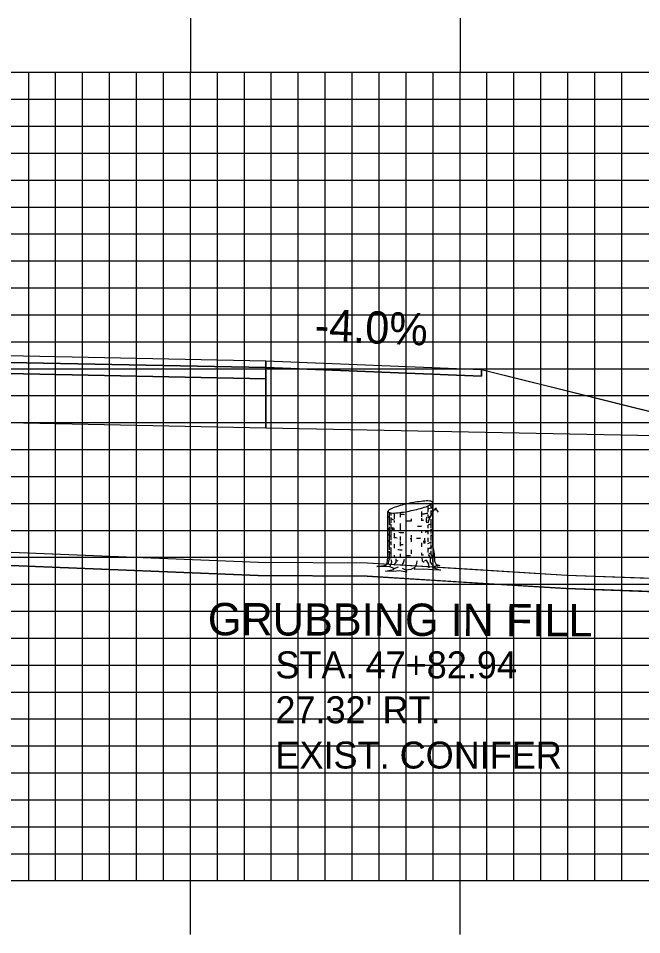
# Model space of a CAD drawing. Extents: x 1754708 to 1755051, y 442591 to 442811.
# Drawn here: x 1754887.13 to 1754910.25, y 442685.31 to 442719.32 of the extents above; entities that cross this region are included whole.
import ezdxf

# ---------------------------------------------------------------- set-up
doc = ezdxf.new("R2010")
doc.units = 0
for name, color, linetype in [('ANNOTATION', 7, 'Continuous'), ('D_Roadway_Edge_Shoulder', 7, 'Continuous'), ('D_Roadway_Edge_TW', 7, 'Continuous'), ('D_Roadway_Pavement', 7, 'Continuous'), ('D_Roadway_SlopeLines', 7, 'Continuous'), ('D_Roadway_SubGrade', 7, 'Continuous'), ('D_Text_Monospaced', 7, 'Continuous'), ('DIMENSIONS', 7, 'Continuous'), ('GRUBBING IN FILL', 7, 'Continuous'), ('M_Trees_Conifer_Pay', 7, 'Continuous'), ('MAJOR', 7, 'Continuous'), ('MINOR', 7, 'Continuous'), ('S_Roadway_Centerline', 7, 'Continuous')]:
    doc.layers.add(name, color=color, linetype=linetype)

msp = doc.modelspace()

# ---------------------------------------------------------------- linework, layer by layer
at = {"layer": 'D_Roadway_Edge_Shoulder'}
msp.add_lwpolyline([(1754896.317, 442706.606), (1754904.317, 442706.286), (1754904.317, 442706.036), (1754896.317, 442706.356)], close=True, dxfattribs=at)
at = {"layer": 'D_Roadway_Edge_TW'}
msp.add_lwpolyline([(1754885.517, 442706.822), (1754896.317, 442706.606), (1754896.317, 442706.356), (1754885.517, 442706.572)], close=True, dxfattribs=at)
at = {"layer": 'D_Roadway_Pavement'}
msp.add_lwpolyline([(1754885.517, 442706.572), (1754896.317, 442706.356), (1754896.317, 442705.94), (1754885.517, 442706.156)], close=True, dxfattribs=at)
msp.add_lwpolyline([(1754896.317, 442706.356), (1754896.317, 442705.94)], dxfattribs=at)
msp.add_lwpolyline([(1754896.317, 442706.356), (1754896.317, 442705.94)], dxfattribs=at)
msp.add_lwpolyline([(1754896.317, 442706.356), (1754896.317, 442705.94)], dxfattribs=at)
at = {"layer": 'D_Roadway_SlopeLines'}
msp.add_lwpolyline([(1754904.317, 442706.286), (1754916.317, 442703.286), (1754936.682, 442698.237)], dxfattribs=at)
at = {"layer": 'D_Roadway_SubGrade'}
for points in [[(1754896.317, 442705.94), (1754896.317, 442706.356), (1754904.317, 442706.036), (1754904.317, 442706.286), (1754914.492, 442703.743), (1754896.317, 442704.106)], [(1754885.517, 442706.156), (1754896.317, 442705.94), (1754896.317, 442704.106), (1754885.517, 442704.322)]]:
    msp.add_lwpolyline(points, close=True, dxfattribs=at)
at = {"layer": 'DIMENSIONS'}
msp.add_line((1754904.317, 442706.286), (1754936.682, 442698.237), dxfattribs=at)
at = {"layer": 'GRUBBING IN FILL'}
msp.add_lwpolyline([(1754843.343, 442701.662), (1754848.865, 442700.485), (1754852.113, 442699.756), (1754854.166, 442698.979), (1754857.625, 442698.75), (1754875.218, 442699.401), (1754875.984, 442699.448), (1754878.886, 442699.328), (1754896.033, 442698.632), (1754900.072, 442698.607), (1754907.451, 442698.155), (1754914.492, 442697.896)], dxfattribs=at)
msp.add_lwpolyline([(1754843.343, 442701.662), (1754848.865, 442700.485), (1754852.113, 442699.756), (1754854.166, 442698.979), (1754857.625, 442698.75), (1754875.218, 442699.401), (1754875.984, 442699.448), (1754878.886, 442699.328), (1754896.033, 442698.632), (1754900.072, 442698.607), (1754907.451, 442698.155), (1754914.492, 442697.896)], dxfattribs=at)
msp.add_lwpolyline([(1754873.517, 442699.839), (1754875.194, 442699.901), (1754875.979, 442699.949), (1754877.443, 442699.888), (1754878.907, 442699.828), (1754887.476, 442699.48), (1754896.045, 442699.132), (1754900.089, 442699.107), (1754903.782, 442698.881), (1754907.475, 442698.655), (1754911.045, 442698.523), (1754914.492, 442698.396), (1754914.492, 442697.896), (1754910.971, 442698.026), (1754907.451, 442698.155), (1754903.761, 442698.381), (1754900.072, 442698.607), (1754896.033, 442698.632), (1754887.459, 442698.98), (1754878.886, 442699.328), (1754875.984, 442699.448), (1754873.517, 442699.338)], close=True, dxfattribs=at)
msp.add_lwpolyline([(1754873.517, 442699.839), (1754875.194, 442699.901), (1754875.979, 442699.949), (1754877.443, 442699.888), (1754878.907, 442699.828), (1754887.476, 442699.48), (1754896.045, 442699.132), (1754900.089, 442699.107), (1754903.782, 442698.881), (1754907.475, 442698.655), (1754911.045, 442698.523), (1754914.492, 442698.396), (1754914.492, 442697.896), (1754910.971, 442698.026), (1754907.451, 442698.155), (1754903.761, 442698.381), (1754900.072, 442698.607), (1754896.033, 442698.632), (1754887.459, 442698.98), (1754878.886, 442699.328), (1754875.984, 442699.448), (1754873.517, 442699.338)], close=True, dxfattribs=at)
at = {"layer": 'M_Trees_Conifer_Pay'}
for p, q in [((1754902.317, 442701.214), (1754902.317, 442700.991)), ((1754902.435, 442701.275), (1754902.435, 442701.113)), ((1754902.506, 442699.701), (1754902.506, 442701.348)), ((1754900.842, 442699.291), (1754900.842, 442701.012)), ((1754900.89, 442700.975), (1754900.89, 442700.504)), ((1754900.948, 442700.964), (1754900.948, 442700.866)), ((1754901.073, 442700.956), (1754901.073, 442700.724)), ((1754901.293, 442700.976), (1754901.293, 442700.808)), ((1754902.089, 442701.018), (1754902.089, 442700.819)), ((1754902.317, 442700.903), (1754902.317, 442700.855)), ((1754902.435, 442701.045), (1754902.435, 442700.917)), ((1754900.948, 442700.792), (1754900.948, 442700.588)), ((1754900.948, 442700.53), (1754900.948, 442700.331)), ((1754901.073, 442700.683), (1754901.073, 442700.609)), ((1754901.293, 442700.571), (1754901.293, 442700.334)), ((1754901.699, 442700.745), (1754901.699, 442700.649)), ((1754902.089, 442700.761), (1754902.089, 442700.672)), ((1754902.317, 442700.52), (1754902.317, 442700.388)), ((1754902.375, 442700.72), (1754902.323, 442700.66)), ((1754902.435, 442700.73), (1754902.435, 442700.394)), ((1754900.89, 442700.439), (1754900.89, 442700.131)), ((1754900.948, 442700.283), (1754900.948, 442699.947)), ((1754901.073, 442700.205), (1754901.073, 442700.067)), ((1754902.089, 442700.325), (1754902.089, 442700.22)), ((1754902.317, 442700.277), (1754902.317, 442700.168)), ((1754902.435, 442700.357), (1754902.435, 442700.195)), ((1754900.89, 442700.084), (1754900.89, 442699.592)), ((1754900.948, 442699.894), (1754900.948, 442699.758)), ((1754901.293, 442700.09), (1754901.293, 442699.938)), ((1754901.293, 442699.894), (1754901.293, 442699.721)), ((1754901.699, 442700.131), (1754901.699, 442700.057)), ((1754901.699, 442700.032), (1754901.699, 442699.884)), ((1754902.089, 442699.853), (1754902.089, 442699.707)), ((1754902.317, 442700.032), (1754902.317, 442699.89)), ((1754902.435, 442700.147), (1754902.435, 442699.931)), ((1754902.435, 442699.9), (1754902.435, 442699.826)), ((1754900.89, 442699.538), (1754900.89, 442699.291)), ((1754900.948, 442699.659), (1754900.948, 442699.281)), ((1754901.073, 442699.795), (1754901.073, 442699.653)), ((1754901.699, 442699.592), (1754901.699, 442699.439)), ((1754902.317, 442699.663), (1754902.317, 442699.491)), ((1754902.435, 442699.785), (1754902.435, 442699.612)), ((1754901.073, 442699.392), (1754901.073, 442699.297)), ((1754901.293, 442699.443), (1754901.293, 442699.291)), ((1754902.089, 442699.474), (1754902.089, 442699.386)), ((1754901.073, 442698.897), (1754901.236, 442698.961)), ((1754901.51, 442698.833), (1754901.384, 442698.897))]:
    msp.add_line(p, q, dxfattribs=at)
for points in [[(1754902.323, 442700.846), (1754902.36, 442700.771), (1754902.407, 442700.829), (1754902.465, 442700.897), (1754902.558, 442701.09), (1754902.622, 442701.138), (1754902.653, 442701.144)], [(1754902.338, 442700.592), (1754902.375, 442700.72), (1754902.438, 442700.835), (1754902.469, 442700.903), (1754902.538, 442701.049)], [(1754902.552, 442701.079), (1754902.628, 442701.086), (1754902.7, 442700.987)], [(1754902.29, 442700.808), (1754902.259, 442700.724), (1754902.255, 442700.656), (1754902.286, 442700.592)], [(1754901.022, 442700.318), (1754901.016, 442700.413), (1754901.059, 442700.39), (1754901.059, 442700.296)], [(1754902.161, 442699.919), (1754902.173, 442699.842), (1754902.22, 442699.853), (1754902.208, 442700.02)], [(1754902.506, 442699.701), (1754902.558, 442699.439), (1754902.574, 442699.165), (1754902.632, 442699.04), (1754902.768, 442699.009), (1754902.537, 442698.972), (1754902.537, 442698.972), (1754902.543, 442698.924), (1754902.791, 442698.83), (1754902.516, 442698.846), (1754902.161, 442698.867), (1754901.839, 442698.856), (1754901.846, 442698.939), (1754901.697, 442698.856), (1754901.51, 442698.833), (1754901.535, 442698.766), (1754901.267, 442698.809), (1754901.046, 442698.782), (1754900.754, 442698.799), (1754901.043, 442698.856), (1754901.073, 442698.897), (1754900.911, 442698.955), (1754900.674, 442698.966), (1754900.433, 442698.966), (1754900.775, 442699.023), (1754900.816, 442699.104), (1754900.842, 442699.291)], [(1754902.432, 442699.558), (1754902.438, 442699.413), (1754902.485, 442699.344), (1754902.496, 442699.145)], [(1754900.89, 442699.243), (1754900.869, 442699.165), (1754900.849, 442699.071)], [(1754900.968, 442699.223), (1754900.974, 442699.107), (1754900.921, 442699.019), (1754900.911, 442698.955)], [(1754901.131, 442699.25), (1754901.131, 442699.118), (1754901.043, 442699.019)], [(1754901.358, 442699.009), (1754901.425, 442699.104), (1754901.452, 442699.243)], [(1754901.846, 442698.939), (1754901.92, 442699.081), (1754901.93, 442699.182)], [(1754902.096, 442699.308), (1754902.107, 442699.182), (1754902.181, 442699.138)], [(1754902.375, 442698.918), (1754902.36, 442699.056), (1754902.286, 442699.186)], [(1754902.333, 442699.413), (1754902.407, 442699.308), (1754902.412, 442699.134), (1754902.537, 442698.972)]]:
    msp.add_lwpolyline(points, dxfattribs=at)
for centre, radius, start, end in [((1754902.698, 442696.245), 5.179, 101.7194, 108.0594), ((1754902.698, 442696.245), 5.179, 95.3794, 101.7194), ((1754900.651, 442706.115), 5.179, 281.7194, 288.0594), ((1754902.288, 442700.603), 0.802, 79.2194, 95.3794), ((1754902.008, 442701.953), 0.802, 288.0594, 304.2194), ((1754902.391, 442701.144), 0.251, 71.0501, 79.2194), ((1754902.318, 442701.498), 0.251, 304.2194, 312.3887), ((1754902.375, 442701.316), 0.172, 300, 311.2506), ((1754902.446, 442701.304), 0.0817, 56.7194, 71.0501), ((1754902.431, 442701.373), 0.0817, 312.3887, 326.7194), ((1754902.447, 442701.233), 0.0624, 311.2506, 330), ((1754902.462, 442701.328), 0.0527, 46.923, 56.7194), ((1754902.476, 442701.344), 0.0314, 34.2194, 46.923), ((1754902.456, 442701.357), 0.0527, 326.7194, 336.5158), ((1754902.463, 442701.224), 0.0441, 330, 343.9485), ((1754902.48, 442701.346), 0.0264, 23.4074, 34.2194), ((1754902.475, 442701.349), 0.0314, 336.5158, 349.2194), ((1754902.484, 442701.348), 0.0226, 11.7194, 23.4074), ((1754902.473, 442701.221), 0.0334, 343.9485, 354.2151), ((1754902.484, 442701.348), 0.0226, 0.0315, 11.7194), ((1754902.48, 442701.348), 0.0264, 349.2194, 0.0315), ((1754900.875, 442700.834), 0.0334, 163.9485, 180), ((1754900.874, 442701.011), 0.0314, 156.5158, 169.2194), ((1754900.869, 442701.012), 0.0264, 169.2194, 180.0315), ((1754900.865, 442701.012), 0.0226, 180.0315, 191.7194), ((1754900.865, 442701.012), 0.0226, 191.7194, 203.4074), ((1754900.869, 442701.014), 0.0264, 203.4074, 214.2194), ((1754900.893, 442701.003), 0.0527, 146.7194, 156.5158), ((1754900.873, 442701.016), 0.0314, 214.2194, 226.923), ((1754900.918, 442700.987), 0.0817, 132.3887, 146.7194), ((1754900.887, 442701.032), 0.0527, 226.923, 236.7194), ((1754900.903, 442701.056), 0.0817, 236.7194, 251.0501), ((1754901.031, 442700.862), 0.251, 124.2194, 132.3887), ((1754900.958, 442701.216), 0.251, 251.0501, 259.2194), ((1754901.341, 442700.406), 0.802, 108.0594, 124.2194), ((1754901.061, 442701.757), 0.802, 259.2194, 275.3794), ((1754900.651, 442706.115), 5.179, 275.3794, 281.7194), ((1754901.675, 442705.024), 4.124, 264.6955, 266.7331), ((1754901.675, 442705.024), 4.124, 276.238, 278.1032), ((1754902.176, 442701.507), 0.571, 278.1032, 284.3667), ((1754902.176, 442701.661), 0.571, 284.4317, 292.4132), ((1754902.176, 442701.507), 0.571, 297.0237, 300), ((1754902.375, 442701.162), 0.172, 300, 311.2506), ((1754902.447, 442701.079), 0.0624, 311.2506, 330), ((1754902.463, 442701.07), 0.0441, 330, 343.9485), ((1754902.473, 442701.067), 0.0334, 343.9485, 354.2151), ((1754900.875, 442700.834), 0.0334, 180, 196.0515), ((1754900.885, 442700.837), 0.0441, 196.0515, 210), ((1754900.901, 442700.846), 0.0624, 210, 228.7494), ((1754900.973, 442700.929), 0.172, 228.7494, 240), ((1754901.172, 442701.274), 0.571, 240, 240.3367), ((1754901.174, 442701.063), 0.571, 240, 247.0587), ((1754901.172, 442701.274), 0.571, 246.8597, 257.9846), ((1754901.673, 442704.791), 4.124, 268.0751, 270), ((1754901.673, 442704.791), 4.124, 270, 270.3581), ((1754901.673, 442704.791), 4.124, 275.7849, 277.0558), ((1754902.175, 442701.063), 0.571, 284.4493, 297.0429), ((1754902.473, 442700.623), 0.0334, 343.9485, 354.2151), ((1754900.875, 442700.387), 0.0334, 163.9485, 180), ((1754900.875, 442700.387), 0.0334, 180, 196.0515), ((1754900.875, 442700.177), 0.0334, 163.9485, 180), ((1754900.875, 442700.177), 0.0334, 180, 196.0515), ((1754900.885, 442700.39), 0.0441, 196.0515, 210), ((1754900.885, 442700.18), 0.0441, 196.0515, 210), ((1754900.901, 442700.399), 0.0624, 210, 228.7494), ((1754900.973, 442700.482), 0.172, 228.7494, 240), ((1754901.172, 442700.827), 0.571, 240, 240.3367), ((1754901.673, 442704.345), 4.124, 264.081, 266.6676), ((1754901.675, 442704.58), 4.124, 273.7052, 275.9504), ((1754901.673, 442704.345), 4.124, 277.6125, 278.1032), ((1754902.174, 442700.827), 0.571, 278.1032, 286.9296), ((1754902.174, 442700.827), 0.571, 297.1896, 300), ((1754902.373, 442700.482), 0.172, 300, 311.2506), ((1754902.446, 442700.399), 0.0624, 311.2506, 330), ((1754902.462, 442700.39), 0.0441, 330, 343.9485), ((1754902.462, 442700.18), 0.0441, 330, 343.9485), ((1754902.472, 442700.387), 0.0334, 343.9485, 354.2151), ((1754902.472, 442700.177), 0.0334, 343.9485, 354.2151), ((1754900.875, 442699.94), 0.0334, 163.9485, 180), ((1754900.875, 442699.94), 0.0334, 180, 196.0515), ((1754900.885, 442699.943), 0.0441, 196.0515, 210), ((1754900.901, 442700.189), 0.0624, 210, 228.7494), ((1754900.901, 442699.953), 0.0624, 210, 228.7494), ((1754900.973, 442700.272), 0.172, 228.7494, 240), ((1754900.973, 442700.035), 0.172, 228.7494, 240), ((1754901.172, 442700.617), 0.571, 240, 246.8597), ((1754901.172, 442700.38), 0.571, 240, 246.8597), ((1754901.172, 442700.617), 0.571, 259.2707, 261.8968), ((1754901.673, 442704.135), 4.124, 261.8968, 263.1474), ((1754901.673, 442704.135), 4.124, 270, 270.3581), ((1754901.673, 442704.135), 4.124, 273.1493, 275.4569), ((1754902.174, 442700.38), 0.571, 285.3983, 297.1896), ((1754902.174, 442700.617), 0.571, 297.1896, 300), ((1754902.373, 442700.272), 0.172, 300, 311.2506), ((1754902.446, 442700.189), 0.0624, 311.2506, 330), ((1754900.875, 442699.743), 0.0334, 163.9485, 180), ((1754900.875, 442699.547), 0.0334, 163.9485, 180), ((1754900.875, 442699.547), 0.0334, 180, 196.0515), ((1754900.885, 442699.55), 0.0441, 196.0515, 210), ((1754900.901, 442699.559), 0.0624, 210, 228.7494), ((1754900.973, 442699.642), 0.172, 228.7494, 240), ((1754901.162, 442700.189), 0.571, 241.2369, 248.0268), ((1754901.172, 442699.987), 0.571, 240, 246.8597), ((1754901.673, 442703.7), 4.124, 263.4991, 265.8397), ((1754901.673, 442703.898), 4.124, 264.716, 266.3193), ((1754902.174, 442700.183), 0.571, 289.2907, 300), ((1754902.373, 442699.838), 0.172, 300, 311.2506), ((1754902.446, 442699.755), 0.0624, 311.2506, 330), ((1754902.462, 442699.746), 0.0441, 330, 343.9485), ((1754902.472, 442699.743), 0.0334, 343.9485, 354.2151), ((1754900.875, 442699.327), 0.0334, 163.9485, 180), ((1754900.875, 442699.327), 0.0334, 180, 196.0515), ((1754900.885, 442699.33), 0.0441, 196.0515, 210), ((1754900.901, 442699.339), 0.0624, 210, 228.7494), ((1754900.973, 442699.422), 0.172, 228.7494, 240), ((1754901.172, 442699.767), 0.571, 240, 244.5314), ((1754901.673, 442703.284), 4.124, 262.4438, 263.512), ((1754901.673, 442703.505), 4.124, 267.8117, 270), ((1754901.673, 442703.505), 4.124, 270, 270.1328), ((1754901.673, 442703.505), 4.124, 275.7849, 276.7896), ((1754901.673, 442703.284), 4.124, 277.3684, 278.1032), ((1754902.174, 442699.767), 0.571, 278.1032, 281.637), ((1754902.174, 442699.987), 0.571, 288.5067, 297.2721), ((1754902.373, 442699.422), 0.172, 300, 311.2506), ((1754902.446, 442699.339), 0.0624, 311.2506, 330), ((1754902.462, 442699.33), 0.0441, 330, 343.9485), ((1754902.472, 442699.327), 0.0334, 343.9485, 354.2151)]:
    msp.add_arc(centre, radius, start, end, dxfattribs=at)
at = {"layer": 'MAJOR'}
for p, q in [((1754893.517, 442719.316), (1754893.517, 442717.312)), ((1754903.517, 442719.316), (1754903.517, 442717.312)), ((1754733.517, 442717.312), (1755013.517, 442717.312)), ((1754733.517, 442717.312), (1755013.517, 442717.312)), ((1754893.517, 442687.312), (1754893.517, 442717.312)), ((1754903.517, 442687.312), (1754903.517, 442717.312)), ((1754733.517, 442712.312), (1755013.517, 442712.312)), ((1754733.517, 442707.312), (1755013.517, 442707.312)), ((1754733.517, 442702.312), (1755013.517, 442702.312)), ((1754733.517, 442697.312), (1755013.517, 442697.312)), ((1754733.517, 442692.312), (1755013.517, 442692.312)), ((1754733.517, 442687.312), (1755013.517, 442687.312)), ((1754733.517, 442687.312), (1755013.517, 442687.312)), ((1754893.517, 442685.308), (1754893.517, 442687.312)), ((1754903.517, 442685.308), (1754903.517, 442687.312))]:
    msp.add_line(p, q, dxfattribs=at)
at = {"layer": 'MINOR'}
for p, q in [((1754887.517, 442687.312), (1754887.517, 442717.312)), ((1754888.517, 442687.312), (1754888.517, 442717.312)), ((1754889.517, 442687.312), (1754889.517, 442717.312)), ((1754890.517, 442687.312), (1754890.517, 442717.312)), ((1754891.517, 442687.312), (1754891.517, 442717.312)), ((1754892.517, 442687.312), (1754892.517, 442717.312)), ((1754894.517, 442687.312), (1754894.517, 442717.312)), ((1754895.517, 442687.312), (1754895.517, 442717.312)), ((1754896.517, 442687.312), (1754896.517, 442717.312)), ((1754897.517, 442687.312), (1754897.517, 442717.312)), ((1754898.517, 442687.312), (1754898.517, 442717.312)), ((1754899.517, 442687.312), (1754899.517, 442717.312)), ((1754900.517, 442687.312), (1754900.517, 442717.312)), ((1754901.517, 442687.312), (1754901.517, 442717.312)), ((1754902.517, 442687.312), (1754902.517, 442717.312)), ((1754904.517, 442687.312), (1754904.517, 442717.312)), ((1754905.517, 442687.312), (1754905.517, 442717.312)), ((1754906.517, 442687.312), (1754906.517, 442717.312)), ((1754907.517, 442687.312), (1754907.517, 442717.312)), ((1754908.517, 442687.312), (1754908.517, 442717.312)), ((1754909.517, 442687.312), (1754909.517, 442717.312)), ((1754733.517, 442716.312), (1755013.517, 442716.312)), ((1754733.517, 442715.312), (1755013.517, 442715.312)), ((1754733.517, 442714.312), (1755013.517, 442714.312)), ((1754733.517, 442713.312), (1755013.517, 442713.312)), ((1754733.517, 442711.312), (1755013.517, 442711.312)), ((1754733.517, 442710.312), (1755013.517, 442710.312)), ((1754733.517, 442709.312), (1755013.517, 442709.312)), ((1754733.517, 442708.312), (1755013.517, 442708.312)), ((1754733.517, 442706.312), (1755013.517, 442706.312)), ((1754733.517, 442705.312), (1755013.517, 442705.312)), ((1754733.517, 442704.312), (1755013.517, 442704.312)), ((1754733.517, 442703.312), (1755013.517, 442703.312)), ((1754733.517, 442701.312), (1755013.517, 442701.312)), ((1754733.517, 442700.312), (1755013.517, 442700.312)), ((1754733.517, 442699.312), (1755013.517, 442699.312)), ((1754733.517, 442698.312), (1755013.517, 442698.312)), ((1754733.517, 442696.312), (1755013.517, 442696.312)), ((1754733.517, 442695.312), (1755013.517, 442695.312)), ((1754733.517, 442694.312), (1755013.517, 442694.312)), ((1754733.517, 442693.312), (1755013.517, 442693.312)), ((1754733.517, 442691.312), (1755013.517, 442691.312)), ((1754733.517, 442690.312), (1755013.517, 442690.312)), ((1754733.517, 442689.312), (1755013.517, 442689.312)), ((1754733.517, 442688.312), (1755013.517, 442688.312))]:
    msp.add_line(p, q, dxfattribs=at)
at = {"layer": 'S_Roadway_Centerline'}
msp.add_lwpolyline([(1754820.805, 442707.13), (1754822.854, 442706.77), (1754825.067, 442706.33), (1754826.524, 442706.037), (1754828.077, 442705.984), (1754832.676, 442704.446), (1754848.972, 442700.973), (1754852.257, 442700.236), (1754854.274, 442699.473), (1754857.632, 442699.25), (1754875.194, 442699.901), (1754875.979, 442699.949), (1754878.907, 442699.828), (1754896.045, 442699.132), (1754900.089, 442699.107), (1754907.475, 442698.655), (1754914.615, 442698.392), (1754927.562, 442698.332), (1754934.194, 442698.29), (1754935.534, 442698.264), (1754937.831, 442698.209), (1754947.484, 442697.842), (1754953.043, 442697.646), (1754970.333, 442697)], dxfattribs=at)

# ---------------------------------------------------------------- texts
at = {"layer": 'ANNOTATION'}
msp.add_text('-4.0%', height=1.2, rotation=357.7094, dxfattribs=at).set_placement((1754898.109, 442707.336))
at = {"layer": 'D_Text_Monospaced'}
for s, height, p in [('STA. 47+82.94', 0.99996, (1754896.669, 442694.822)), ("27.32' RT.", 1, (1754896.669, 442693.154)), ('EXIST. CONIFER', 0.99996, (1754896.669, 442691.474))]:
    msp.add_text(s, height=height, dxfattribs=at).set_placement(p)
at = {"layer": 'GRUBBING IN FILL'}
msp.add_text('GRUBBING IN FILL', height=1.2, rotation=359.8142, dxfattribs=at).set_placement((1754894.161, 442696.42))

doc.saveas('drawing.dxf')
